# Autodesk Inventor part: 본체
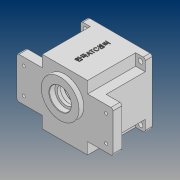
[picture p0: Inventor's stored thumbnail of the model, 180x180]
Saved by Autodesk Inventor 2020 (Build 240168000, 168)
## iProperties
Created: 2020-07
Part Number: 본체
Material: 일반
Document SubType Name: Modeling
Designer: PC312-02
Density: 1 g/cm^3
Appearance: 기본값
Mass: 324.634 g
Surface Area: 793.575 cm^2
Volume: 324.634 cm^3
Author: PC312-02
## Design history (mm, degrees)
sketch "스케치1"
  geometry: L1 (33, -47)-(-33, -47); L2 (-33, 47)-(33, 47); L3 (-70, -30)-(-70, 30); L4 (70, 30)-(70, -30); L5 (-33, -47)-(-33, -30); L6 (-33, 30)-(-33, 47); L7 (33, 47)-(33, 30); L8 (33, -30)-(33, -47); L9 (-70, 30)-(-33, 30); L10 (33, 30)-(70, 30); L11 (70, -30)-(33, -30); L12 (-33, -30)-(-70, -30); 1 further point
  constraints: 24 end point, 10 parallel, 4 perpendicular, 3 horizontal
  dimensions: "d0" = 66 distance of L2.start L2.end; "d1" = 94 distance of L1.end L2.start; "d2" = 140 distance of L3.end L4.start; "d3" = 60 distance of L3.start L3.end; "d4" = 33 distance from line of L5 point (0, 0); "d5" = 33 distance from line of L8 point (0, 0); "d6" = 47 distance from line of point (0, 0) L1; "d7" = 47 distance from line of point (0, 0) L2; "d8" = 70 distance from line of point (0, 0) L4; "d9" = 140 distance between parallel lines of L3 L4; "d10" = 30 distance from line of point (0, 0) L11; "d11" = 60 distance between parallel lines of L10 L11
extrude "돌출1" new body sketch "스케치1" distance "d12" = 13; taper "d13" = 0 deg
sketch "스케치2"
  geometry: L1 (-33, 30)-(-33, 47) reference; L2 (33, -47)-(-33, -47); L3 (-33, 47)-(33, 47); L4 (-70, 30)-(-33, 30) reference; L5 (-47, -30)-(-47, 30); L6 (47, 30)-(47, -30); L7 (-47, 30)-(-33, 30); L8 (33, 30)-(47, 30); L9 (-33, -47)-(-33, -30); L10 (-33, 30)-(-33, 47); L11 (33, 47)-(33, 30); L12 (33, -30)-(33, -47); L13 (47, -30)-(33, -30); L14 (-33, -30)-(-47, -30); 1 further point
  constraints: 24 end point, 10 parallel, 4 perpendicular, 3 horizontal, 1 point on line
  dimensions: "d14" = 94 distance between parallel lines of L2 L3; "d16" = 94 distance between parallel lines of L6 L5; "d17" = 47 distance from line of point (0, 0) L5; "d18" = 30 distance from line of point (0, 0) L8; "d19" = 60 distance between parallel lines of L13 L8; "d20" = 66 distance between parallel lines of L1 L11; "d21" = 66 distance between parallel lines of L9 L12; "d22" = 33 distance from line of point (0, 0) L12; "d23" = 30 distance from line of point (0, 0) L14
extrude "돌출2" join sketch "스케치2" distance "d24" = 57; taper "d25" = 0 deg
sketch "스케치3"
  geometry: L1 (47, -47)-(-47, -47); L2 (-47, -47)-(-47, 47); L3 (-47, 47)-(47, 47); L4 (47, 47)-(47, -47); L5 (47, -47)-(-47, 47); L6 (-47, -47)-(47, 47); 1 further point
  constraints: 12 end point, 2 midpoint, 2 parallel, 1 horizontal, 1 perpendicular
  dimensions: "d26" = 94 distance of L2.end L3.end; "d27" = 94 distance of L1.end L2.end
extrude "돌출3" join sketch "스케치3" distance "d28" = 10; taper "d29" = 0 deg
sketch "스케치4"
  geometry: C1 r 27.5 at (0, 11); 1 further point
  constraints: 1 centre point, 1 vertical alignment
  dimensions: "d30" = 55 diameter of C1; "d31" = 11 distance of point (0, 0) C1.centre
extrude "돌출4" join sketch "스케치4" distance "d32" = 7; taper "d33" = 0 deg
sketch "스케치5"
  geometry: L1 (38.5, 20)-(-16.5, 20) reference; L2 (11, 20)-(11, -3); L3 (27, 20)-(27, 11.7); L4 (27, 11.7)-(23.5, 11.7); L5 (23.5, 11.7)-(23.5, 7); L6 (23.5, 7)-(28.5, 7); L7 (28.5, 7)-(28.5, -3); L8 (28.5, -3)-(11, -3); L9 (27, 20)-(11, 20); L10 (-20, 7)-(-20, -3); L11 (-9, -3)-(-9, 4); L12 (-9, 4)-(-10.5, 4); L13 (-10.5, 4)-(-10.5, 7); L14 (-10.5, 7)-(-20, 7); L15 (-9, -3)-(-20, -3); 1 further point
  constraints: 28 end point, 7 horizontal, 7 vertical, 3 horizontal alignment, 1 midpoint, 1 point on line
  dimensions: "d34" = 32 diameter of L3 L2; "d35" = 25 diameter of L5 L2; "d36" = 35 diameter of L7 L2; "d37" = 8.3 distance between parallel lines of L4 L1; "d38" = 10 distance between parallel lines of L8 L6; "d39" = 23 distance between parallel lines of L8 L1; "d40" = 31 distance from line of L10.end L2; "d41" = 22 diameter of L11 L10; "d42" = 19 diameter of L13 L10; "d43" = 7 distance from line of L11.start L12; "d44" = 3 distance between parallel lines of L14 L12
revolve "회전1" stored, may be unused: angle "d45" = 90 deg
revolve "회전2" stored, may be unused: angle "d46" = 90 deg
sketch "스케치6"
  geometry: C1 r 43 at (0, 0); 1 further point
  constraints: 1 centre point, 1 coincident
  dimensions: "d47" = 86 diameter of C1
extrude "돌출5" cut sketch "스케치6" distance "d48" = 9; taper "d49" = 0 deg
sketch "스케치7"
  geometry: L1 (36, 4)-(39.799, 4); L2 (36, -4)-(39.799, -4); L3 (0, 40)-(0, 0); L4 (0, 0)-(0, -40); L5 (-36, 4)-(-39.799, 4); L6 (-36, -4)-(-39.799, -4); A1 r 4 centre (36, 0) between (36, 4) and (36, -4); A2 r 4 centre (-36, 0) between (-36, -4) and (-36, 4); A3 r 40 centre (0, 0) between (-39.799, -4) and (39.799, -4); A4 r 40 centre (0, 0) between (39.799, 4) and (-39.799, 4); A5 r 21 centre (0, 11) between (8.978, -7.984) and (-8.978, -7.984); A6 r 15 centre (0, -20) between (-8.978, -7.984) and (8.978, -7.984); 3 further points
  constraints: 14 point on circle, 12 end point, 6 centre point, 5 symmetric about line, 3 coincident, 2 horizontal, 2 tangent, 2 vertical, 1 horizontal alignment, 1 other
  dimensions: "d53" = 36 distance of point (0, 0) A1.centre; "d54" = 8 diameter of A1; "d56" = 40 radius of A3; "d57" = 40 radius of A4; "d58" = 42 diameter of A5; "d59" = 30 diameter of A6
extrude "돌출6" cut sketch "스케치7" distance "d60" = 62; taper "d61" = 0 deg
sketch "스케치8"
  geometry: C1 r 17.5 at (0, 11) reference; C2 r 11 at (0, -20) reference; A1 r 21 centre (0, 11) between (8.978, -7.984) and (-8.978, -7.984); A2 r 15 centre (0, -20) between (-8.978, -7.984) and (8.978, -7.984); 1 further point
  constraints: 4 point on circle, 2 centre point, 2 coincident
  dimensions: "d64" = 30 diameter of A2; "d65" = 42 diameter of A1
extrude "돌출7" cut sketch "스케치8" distance "d62" = 55; taper "d63" = 0 deg
sketch "스케치11"
  geometry: 2 further points
  dimensions: "d66" = 60 horizontal distance of point (0, 0) point (-60, 19); "d67" = 19 vertical distance of point (-60, 19) point (0, 0)
hole "구멍1" sketch "스케치11" at (-60, 19) diameter "d68" = 4.5; stored, may be unused: countersink angle "d72" = 90 deg, drill point angle "d74" = 0 deg; dims "d69" = 8, "d70" = 10, "d71" = 5, "d73" = 13
sketch "스케치12"
  geometry: A1 r 4 centre (-36, 0) between (-36, -4) and (-36, 4) reference; 2 further points
  constraints: 1 coincident
hole "구멍2" sketch "스케치12" at (-36, 0) diameter "d81" = 3.242; stored, may be unused: countersink angle "d85" = 90 deg, drill point angle "d87" = 118 deg; dims "d82" = 7, "d83" = 10, "d84" = 5, "d86" = 9
sketch "스케치13"
  geometry: C1 r 3.5 at (40, 40); 1 further point
  constraints: 1 centre point
  dimensions: "d88" = 7 diameter of C1; "d89" = 40 horizontal distance of C1.centre point (0, 0); "d90" = 40 horizontal distance of C1.centre point (0, 0)
extrude "돌출8" cut sketch "스케치13" extent not by distance; stored distance "d91" = 0; taper "d92" = 0 deg
fillet "모깎기1" dims "d99" = 3
fillet "모깎기2" dims "d100" = 3
chamfer "모따기1" distance "d101" = 1; stored, may be unused: second distance "d102" = 2, angle "d103" = 45 deg
chamfer "모따기2" distance "d104" = 0.8; stored, may be unused: second distance "d105" = 2, angle "d106" = 30 deg
fillet "모깎기3" dims "d107" = 3
node "작업 평면1"
sketch "스케치14"
  geometry: L1 (-11, 80)-(77, 80) reference; 2 further points
  constraints: 1 vertical alignment, 1 other
  dimensions: "d109" = 40 distance from line of L1 point (33, 40)
feature "엠보싱1" sketch "스케치14" dims "d0" = 66, "d1" = 94, "d2" = 140, "d3" = 60, "d4" = 33, "d5" = 33, "d6" = 47, "d7" = 47, "d8" = 70, "d9" = 140, "d10" = 30, "d11" = 60, "d110" = 0.5, "d111" = 0
chamfer "모따기3" distance "d112" = 1; stored, may be unused: second distance "d113" = 2, angle "d114" = 45 deg
node "솔리드1"
pattern_linear "직사각형 패턴1" dims "d77" = 38, "d80" = 120
mirror "미러1"
pattern_linear "직사각형 패턴2" dims "d95" = 80, "d98" = 80
feature "A9D066F2-1C7D-4E18-AEED-F7BC21143FA4" dims "d68" = 4.5, "d69" = 8, "d70" = 10, "d71" = 5, "d72" = 90 deg, "d73" = 13, "d74" = 0
